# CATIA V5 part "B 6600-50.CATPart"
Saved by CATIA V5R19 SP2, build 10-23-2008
Part number: B 6600-50
Bounding box of the stored display mesh (mm): x -59.975 to 59.975, y -59.975 to 59.975, z 0 to 240
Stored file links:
  C:\Users\Bora\Desktop\3D Katı model\B serisi\B 6600\B 6600-50.CATPart
  C:\Program Files\Dassault Systemes\B19\intel_a\reffiles\standard\MetricThickPitch.txt
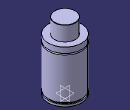
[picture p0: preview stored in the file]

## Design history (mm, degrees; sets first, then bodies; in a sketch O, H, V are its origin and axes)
Body1 (main body)
  Sketch1 on yz-plane, origin (0, 0, 0), H (0, 1, 0), V (0, 0, 1)
    point P3 (37.5, 239)
    point P5 (37.5, 239)
    point P10 (60, 162)
    point P11 (60, 167)
    point P13 (60, 167)
    point P14 (60, 162)
    line L1 (60, 0) -> (60, 8)
    line L2 (37.5, 239) -> (37.5, 187)
    arc A1 centre (36.5, 239) radius 1 from (37.5, 239) to (36.5, 240) ccw
    line L3 (56, 13) -> (56, 8)
    line L4 (60, 13) -> (60, 162)
    line L5 (60, 167) -> (60, 187)
    arc A2 centre (60, 164.5) radius 2.5 from (60, 167) to (60, 162) ccw
    line L6 (36.5, 240) -> (0, 240)
    point P15 (0, 240)
    line L7 (37.5, 187) -> (60, 187)
    line L8 (0, 0) -> (60, 0)
    line L9 (56, 13) -> (60, 13)
    line L10 (56, 8) -> (60, 8)
    coincidence: P15 V, P3 P5, P10 P14, P11 P13
    tangency: L6 A1
    horizontal: L7 H, L8 H, L9 H, L10 H
  Shaft1: profile Sketch1, axis Sketch1.V, angle 360
  Sketch2 on face of Shaft1 from Sketch1.L8, origin (0, 0, 0), H (1, 0, 0), V (0, -1, 0)
    point P1 (40, 0)
    distance P1 V = 40
  Hole1: placed by Sketch2, at (40, 0, 0) direction (0, 0, 1), diameter 8.376, depth 16, threaded "M10", thread diameter 10, thread depth 16, pitch 1.5
  CircPattern1: of Hole1, instances 4, angular step 90, axis from xy-plane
